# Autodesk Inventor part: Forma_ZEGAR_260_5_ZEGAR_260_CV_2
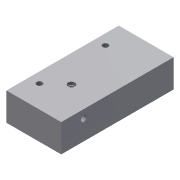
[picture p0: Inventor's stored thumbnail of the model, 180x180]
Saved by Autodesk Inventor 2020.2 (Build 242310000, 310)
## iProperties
Created: 2015-01
Part Number: Forma_ZEGAR_260_5_ZEGAR_260_CV_2
Material: Ogólny
Document SubType Name: Modeling
Designer: F.Stasiak
Density: 1 g/cm^3
Appearance: Domyślna
Catalog Web Link: www.expertbooks.pl
Manager: www.cadconsulting.pl
Company: Fabian Stasiak CAD Consulting
Author: F.Stasiak
Subject: Zbiór ćwiczeń. Autodesk Inventor 2020. Kurs Professional
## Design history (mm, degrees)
node "Forma_ZEGAR_260_4_ZEGAR_260_CV_Base"
feature "Rzeźbienie4"
feature "Gwint1" dims "d0" = 0, "d1" = 0
feature "Rzeźbienie6"
feature "Gwint3" dims "d4" = 0, "d5" = 0
feature "Rzeźbienie9"
feature "Rzeźbienie12"
feature "Bryła1::Forma_ZEGAR_260_4_ZEGAR_260_CV_Base"
tag "Bryła wyprowadzona1"
node "Bryła1"
feature "Forma_ZEGAR_260_4_ZEGAR_260_CV_Base_Bodies"
feature "Powierzchnia4"
body "Srf4"
feature "Powierzchnia6"
body "Srf6"
feature "Powierzchnia9"
body "Srf9"
feature "Powierzchnia12"
body "Srf12"
